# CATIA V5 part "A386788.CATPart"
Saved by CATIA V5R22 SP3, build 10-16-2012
Part number: EPXB2PB13N
Revision: A
Definition: A386788
Nomenclature: CONNECTOR, PLUG, SHELL, 2 CAVITY
Source: bought
Description: CONNECTOR, PLUG, SHELL, 2 CAVITY
Publications: "Logical Termination.1", "Logical Pin.1", "CaCP1", "CaCP A_generated(CaCP1)", "Ca A Coincident_generated(CaCP1)", "Ca A Direction_generated(CaCP1)", "CaCP2", "CaCP B_generated(CaCP2)", "Ca B Coincident_generated(CaCP2)", "Ca B Direction_generated(CaCP2)", "BaCP", "BaCP_generated(BaCP)", "Face_generated(BaCP)", "BaCP Coincident_generated(BaCP)", "BaCP Direction_generated(BaCP)"
Material "Density=.1010": density 2795.67 kg/m3
Bounding box of the stored display mesh (mm): x -44.006 to 44.006, y -14.097 to 21.844, z -9.512 to 9.512
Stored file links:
  C:\Users\u305772\OneDrive - Gulfstream Aerospace\AD PAG\Harness\A386788.CATPart
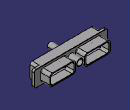
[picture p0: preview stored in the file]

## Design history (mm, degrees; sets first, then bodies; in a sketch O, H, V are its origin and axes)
Parameters
  PartNumber = "EPXB2PB13N"
  OtherKeywords = "CONNECTOR, SHELL, PLUG, 2 CAVITY"
  Comments = "SHELL, PLUG, 2 CAVITY, ALUMINUM ALLOY, NICKEL PLATED"
  CAGECode = "F0987"
  WeightComment = "CALCULATED FROM CATIA"
  WeightSource = "Calculated"
  Volume = 1.15248e-05 (volume) {= smartVolume(Body1)}
  Density = 2795.67 (density)
  Weight = 0.08
AxisSystem1 "CCP": origin (0, 21.844, 1.5011), X (0, 1, 0), Y (-1, 0, 0), Z (0, 0, 1)
Set1
  Point1 "CaCP A": type OnPlane, Support end face of Pocket2, RefPoint sketch element, H 0, V 0, Direction (1, 0, 0)
  Point2 "CaCP B": type OnPlane, Support end face of Pocket2, RefPoint sketch element, H 0, V 0, Direction (1, 0, 0)
  Line1 "Ca A Coincident": type PtDir, RefPoint Point1, Direction (0, 1, 0), Start 0, End 6.35
  Line2 "Ca A Direction": type PtDir, RefPoint Point1, Direction (0, 0, 1), Start 0, End 6.35
  Line3 "Ca B Coincident": type PtDir, RefPoint Point2, Direction (0, 1, 0), Start 0, End 6.35
  Line4 "Ca B Direction": type PtDir, RefPoint Point2, Direction (0, 0, 1), Start 0, End 6.35
  Point3 "CCP": type Center, Curve edge [end face of Pad4 | face of Pad4 from Sketch6.A2]
  Line5 "CCP Coincident": type PtDir, RefPoint Point3, Direction (0, 1, 0), Start 0, End 6.35
  Line6 "CCP Direction": type PtDir, RefPoint Point3, Direction (0, 0, 1), Start 0, End 6.35
  Point4 "BaCP": type OnPlane, Support start face of Pad1, H 0, V 0, Direction (1, 0, 0)
  Line7 "BaCP Coincident": type PtDir, RefPoint Point4, Direction (0, 1, 0), Start 0, End 6.35
  Line8 "BaCP Direction": type PtDir, RefPoint Point4, Direction (0, 0, 1), Start 0, End 6.35
Body1 (main body)
  Sketch1 on zx-plane, origin (0, 0, 0), H (-1, 0, 0), V (0, 0, 1)
    line L1 (37.9222, 6.9723) -> (37.9222, -6.9723)
    line L2 (35.3822, -9.5123) -> (-35.3822, -9.5123)
    line L3 (-37.9222, -6.9723) -> (-37.9222, 6.9723)
    line L4 (-35.3822, 9.5123) -> (35.3822, 9.5123)
    arc A1 centre (35.3822, 6.9723) radius 2.54 from (37.9222, 6.9723) to (35.3822, 9.5123) ccw
    arc A2 centre (35.3822, -6.9723) radius 2.54 from (37.9222, -6.9723) to (35.3822, -9.5123) cw
    arc A3 centre (-35.3822, -6.9723) radius 2.54 from (-35.3822, -9.5123) to (-37.9222, -6.9723) cw
    arc A4 centre (-35.3822, 6.9723) radius 2.54 from (-37.9222, 6.9723) to (-35.3822, 9.5123) cw
    radius A1 = 2.54
    radius A2 = 2.54 {= Sketch1.radius(A1)}
    radius A3 = 2.54 {= Sketch1.radius(A1)}
    radius A4 = 2.54 {= Sketch1.radius(A1)}
    distance L4 L2 = 19.0246
    distance L1 L3 = 75.8444
    vertical: L1 V, L3 V
    horizontal: L2 H, L4 H
    equidistance: L1 L3 O, L2 L4 O
    tangency: A1 L1, A1 L4, A2 L1, A2 L2, A3 L2, A3 L3, A4 L3, A4 L4
  Pad1: profile Sketch1, direction (0, 1, 0), length 8.001
  Sketch2 on end face of Pad1, origin (0, 8.001, 0), H (-1, 0, 0), V (0, 0, 1)
    line L1 (44.0055, 6.9723) -> (44.0055, -6.9723)
    line L2 (41.4655, -9.5123) -> (-41.4655, -9.5123)
    line L3 (-44.0055, -6.9723) -> (-44.0055, 6.9723)
    line L4 (-41.4655, 9.5123) -> (41.4655, 9.5123)
    arc A1 centre (41.4655, 6.9723) radius 2.54 from (44.0055, 6.9723) to (41.4655, 9.5123) ccw
    arc A2 centre (41.4655, -6.9723) radius 2.54 from (44.0055, -6.9723) to (41.4655, -9.5123) cw
    arc A3 centre (-41.4655, -6.9723) radius 2.54 from (-41.4655, -9.5123) to (-44.0055, -6.9723) cw
    arc A4 centre (-41.4655, 6.9723) radius 2.54 from (-44.0055, 6.9723) to (-41.4655, 9.5123) cw
    reference projected line E1 (35.3822, 9.5123) -> (-35.3822, 9.5123) from edge [face of Pad1 from Sketch1.L4 | end face of Pad1]
    radius A1 = 2.54
    radius A2 = 2.54 {= Sketch2.radius(A1)}
    radius A3 = 2.54 {= Sketch2.radius(A1)}
    radius A4 = 2.54 {= Sketch2.radius(A1)}
    distance L1 L3 = 88.011
    vertical: L1 V, L3 V
    horizontal: L2 H, L4 H
    equidistance: L1 L3 O, L2 L4 O
    tangency: A1 L1, A1 L4, A2 L1, A2 L2, A3 L2, A3 L3, A4 L3, A4 L4
    coincidence: L4 E1
  Pad2: profile Sketch2, direction (0, 1, 0), length 3.048
  Sketch3 on end face of Pad2, origin (0, 11.049, 0), H (-1, 0, 0), V (0, 0, 1)
    point P1 (-20.9233, 0)
    line L1 (-5.4737, 3.8608) -> (-5.4737, -3.8608)
    line L2 (-8.5725, -6.9596) -> (-33.274, -6.9596)
    line L3 (-36.3728, -3.8608) -> (-36.3728, 3.8608)
    line L4 (-33.274, 6.9596) -> (-8.5725, 6.9596)
    point P2 (-5.4737, 6.9596)
    point P3 (-5.4737, -6.9596)
    point P4 (-36.3728, -6.9596)
    point P5 (-36.3728, 6.9596)
    point P6 (5.4737, -6.9596)
    point P7 (5.4737, 6.9596)
    line L5 (5.4737, 3.8608) -> (5.4737, -3.8608)
    point P8 (36.3728, -6.9596)
    line L6 (8.5725, -6.9596) -> (33.274, -6.9596)
    point P9 (36.3728, 6.9596)
    line L7 (36.3728, -3.8608) -> (36.3728, 3.8608)
    line L8 (33.274, 6.9596) -> (8.5725, 6.9596)
    point P10 (20.9233, 0)
    arc A1 centre (-8.5725, 3.8608) radius 3.0988 from (-5.4737, 3.8608) to (-8.5725, 6.9596) ccw
    arc A2 centre (-8.5725, -3.8608) radius 3.0988 from (-5.4737, -3.8608) to (-8.5725, -6.9596) cw
    arc A3 centre (-33.274, -3.8608) radius 3.0988 from (-33.274, -6.9596) to (-36.3728, -3.8608) cw
    arc A4 centre (-33.274, 3.8608) radius 3.0988 from (-36.3728, 3.8608) to (-33.274, 6.9596) cw
    arc A5 centre (8.5725, -3.8608) radius 3.0988 from (5.4737, -3.8608) to (8.5725, -6.9596) ccw
    arc A6 centre (8.5725, 3.8608) radius 3.0988 from (5.4737, 3.8608) to (8.5725, 6.9596) cw
    arc A7 centre (33.274, -3.8608) radius 3.0988 from (33.274, -6.9596) to (36.3728, -3.8608) ccw
    arc A8 centre (33.274, 3.8608) radius 3.0988 from (36.3728, 3.8608) to (33.274, 6.9596) ccw
    distance L5 L1 = 10.9474
    distance L7 L3 = 72.7456
    distance L8 L6 = 13.9192
    radius A1 = 3.0988
    radius A2 = 3.0988 {= Sketch3.radius(A1)}
    radius A3 = 3.0988 {= Sketch3.radius(A1)}
    radius A4 = 3.0988 {= Sketch3.radius(A1)}
    radius A5 = 3.0988 {= Sketch3.radius(A1)}
    radius A6 = 3.0988 {= Sketch3.radius(A1)}
    radius A7 = 3.0988 {= Sketch3.radius(A1)}
    radius A8 = 3.0988 {= Sketch3.radius(A1)}
    coincidence: P1 H, L1 P2, L4 P2, L1 P3, L2 P3, L2 P4, L3 P4, L3 P5, L4 P5, L5 P6, L6 P6, L5 P7, L8 P7, L6 P8, L7 P8, L7 P9, L8 P9
    vertical: L1 V, L3 V
    horizontal: L2 H, L4 H
    equidistance: L1 L3 P1, L2 L4 P1
    symmetry: P3 P6 V, P2 P7 V, L1 L5 V, P4 P8 V, L2 L6 V, P5 P9 V, L3 L7 V, L4 L8 V, P1 P10 V
    tangency: A1 L1, A1 L4, A2 L1, A2 L2, A3 L2, A3 L3, A4 L3, A4 L4, A5 L5, A5 L6, A6 L5, A6 L8, A7 L6, A7 L7, A8 L7, A8 L8
  Pad3: profile Sketch3, direction (0, 1, 0), length 10.795
  Sketch4 on end face of Pad3, origin (0, 21.844, 0), H (-1, 0, 0), V (0, 0, 1)
    point P1 (-20.9233, 0)
    line L1 (-7.0739, 3.3274) -> (-7.0739, -3.3274)
    line L2 (-9.4615, -5.715) -> (-32.385, -5.715)
    line L3 (-34.7726, -3.3274) -> (-34.7726, 3.3274)
    line L4 (-32.385, 5.715) -> (-9.4615, 5.715)
    arc A1 centre (-9.4615, 3.3274) radius 2.3876 from (-7.0739, 3.3274) to (-9.4615, 5.715) ccw
    point P2 (-7.0739, 3.3274)
    point P3 (-9.4615, 5.715)
    arc A2 centre (-9.4615, -3.3274) radius 2.3876 from (-7.0739, -3.3274) to (-9.4615, -5.715) cw
    point P5 (-7.0739, -3.3274)
    point P6 (-9.4615, -5.715)
    arc A3 centre (-32.385, -3.3274) radius 2.3876 from (-32.385, -5.715) to (-34.7726, -3.3274) cw
    point P8 (-32.385, -5.715)
    point P9 (-34.7726, -3.3274)
    arc A4 centre (-32.385, 3.3274) radius 2.3876 from (-34.7726, 3.3274) to (-32.385, 5.715) cw
    point P11 (-34.7726, 3.3274)
    point P12 (-32.385, 5.715)
    point P14 (20.9233, 0)
    point P15 (7.0739, 3.3274)
    point P16 (9.4615, 5.715)
    point P18 (7.0739, -3.3274)
    point P19 (9.4615, -5.715)
    point P21 (32.385, -5.715)
    point P22 (34.7726, -3.3274)
    point P24 (34.7726, 3.3274)
    point P25 (32.385, 5.715)
    line L5 (7.0739, 3.3274) -> (7.0739, -3.3274)
    line L6 (9.4615, -5.715) -> (32.385, -5.715)
    line L7 (34.7726, -3.3274) -> (34.7726, 3.3274)
    line L8 (32.385, 5.715) -> (9.4615, 5.715)
    arc A5 centre (9.4615, 3.3274) radius 2.3876 from (7.0739, 3.3274) to (9.4615, 5.715) cw
    arc A6 centre (9.4615, -3.3274) radius 2.3876 from (7.0739, -3.3274) to (9.4615, -5.715) ccw
    arc A7 centre (32.385, -3.3274) radius 2.3876 from (32.385, -5.715) to (34.7726, -3.3274) ccw
    arc A8 centre (32.385, 3.3274) radius 2.3876 from (34.7726, 3.3274) to (32.385, 5.715) ccw
    reference projected line E1 (5.4737, 4.4196) -> (5.4737, -4.4196) from edge [face of Pad3 from Sketch3.L5 | end face of Pad3]
    reference projected line E2 (36.3728, -4.4196) -> (36.3728, 4.4196) from edge [face of Pad3 from Sketch3.L7 | end face of Pad3]
    radius A1 = 2.3876
    radius A2 = 2.3876 {= Sketch4.radius(A1)}
    radius A3 = 2.3876 {= Sketch4.radius(A1)}
    radius A4 = 2.3876 {= Sketch4.radius(A1)}
    distance L4 L2 = 11.43
    distance L5 E1 = 1.6002
    distance E2 L7 = 1.6002
    coincidence: P1 H
    vertical: L1 V, L3 V
    horizontal: L2 H, L4 H
    equidistance: L1 L3 P1, L2 L4 P1
    tangency: A1 L1, A1 L4, A2 L1, A2 L2, A3 L2, A3 L3, A4 L3, A4 L4
    symmetry: P1 P14 V, P2 P15 V, P3 P16 V, P5 P18 V, P6 P19 V, P8 P21 V, P9 P22 V, P11 P24 V, P12 P25 V, L1 L5 V, L2 L6 V, L3 L7 V, L4 L8 V, A1 A5 V, A2 A6 V, A3 A7 V, A4 A8 V
  Pocket1: profile Sketch4, direction (0, -1, 0), through (limit type 6)
  Sketch5 on start face of Pad1, origin (0, 0, 0), H (1, 0, 0), V (0, 0, 1)
    point P1 (-20.8661, 0)
    line L1 (-5.969, 5.2451) -> (-5.969, -5.2451)
    line L2 (-6.7564, -6.0325) -> (-34.9758, -6.0325)
    line L3 (-35.7632, -5.2451) -> (-35.7632, 5.2451)
    line L4 (-34.9758, 6.0325) -> (-6.7564, 6.0325)
    arc A1 centre (-6.7564, 5.2451) radius 0.7874 from (-5.969, 5.2451) to (-6.7564, 6.0325) ccw
    point P2 (-5.969, 5.2451)
    point P3 (-6.7564, 6.0325)
    arc A2 centre (-6.7564, -5.2451) radius 0.7874 from (-5.969, -5.2451) to (-6.7564, -6.0325) cw
    point P5 (-5.969, -5.2451)
    point P6 (-6.7564, -6.0325)
    arc A3 centre (-34.9758, -5.2451) radius 0.7874 from (-34.9758, -6.0325) to (-35.7632, -5.2451) cw
    point P8 (-34.9758, -6.0325)
    point P9 (-35.7632, -5.2451)
    arc A4 centre (-34.9758, 5.2451) radius 0.7874 from (-35.7632, 5.2451) to (-34.9758, 6.0325) cw
    point P11 (-35.7632, 5.2451)
    point P12 (-34.9758, 6.0325)
    reference projected line E1 (-37.9222, -6.8707) -> (-37.9222, 6.8707) from edge [start face of Pad1 | face of Pad1 from Sketch1.L1]
    point P14 (20.8661, 0)
    point P15 (5.969, 5.2451)
    point P16 (6.7564, 6.0325)
    point P18 (5.969, -5.2451)
    point P19 (6.7564, -6.0325)
    point P21 (34.9758, -6.0325)
    point P22 (35.7632, -5.2451)
    point P24 (35.7632, 5.2451)
    point P25 (34.9758, 6.0325)
    line L5 (5.969, 5.2451) -> (5.969, -5.2451)
    line L6 (6.7564, -6.0325) -> (34.9758, -6.0325)
    line L7 (35.7632, -5.2451) -> (35.7632, 5.2451)
    line L8 (34.9758, 6.0325) -> (6.7564, 6.0325)
    arc A5 centre (6.7564, 5.2451) radius 0.7874 from (5.969, 5.2451) to (6.7564, 6.0325) cw
    arc A6 centre (6.7564, -5.2451) radius 0.7874 from (5.969, -5.2451) to (6.7564, -6.0325) ccw
    arc A7 centre (34.9758, -5.2451) radius 0.7874 from (34.9758, -6.0325) to (35.7632, -5.2451) ccw
    arc A8 centre (34.9758, 5.2451) radius 0.7874 from (35.7632, 5.2451) to (34.9758, 6.0325) ccw
    radius A1 = 0.7874
    radius A2 = 0.7874 {= Sketch5.radius(A1)}
    radius A3 = 0.7874 {= Sketch5.radius(A1)}
    radius A4 = 0.7874 {= Sketch5.radius(A1)}
    distance L3 E1 = 2.159
    distance L5 L1 = 11.938
    distance L4 L2 = 12.065
    coincidence: P1 H
    vertical: L1 V, L3 V
    horizontal: L2 H, L4 H
    equidistance: L1 L3 P1, L2 L4 P1
    tangency: A1 L1, A1 L4, A2 L1, A2 L2, A3 L2, A3 L3, A4 L3, A4 L4
    symmetry: P1 P14 V, P2 P15 V, P3 P16 V, P5 P18 V, P6 P19 V, P8 P21 V, P9 P22 V, P11 P24 V, P12 P25 V, L1 L5 V, L2 L6 V, L3 L7 V, L4 L8 V, A1 A5 V, A2 A6 V, A3 A7 V, A4 A8 V
  Pocket2: profile Sketch5, direction (0, 1, 0), length 12.2428
  Sketch6 on end face of Pad2, origin (0, 11.049, 0), H (-1, 0, 0), V (0, 0, 1)
    circle A1 centre (0, 1.5011) radius 3.9751
    point P1 (0, 1.5011)
    circle A2 centre (0, 1.5011) radius 3.3401
    point P2 (20.9233, 0)
    reference projected line E1 (33.9852, 5.715) -> (7.8613, 5.715) from edge [end face of Pad3 | face of Pocket1 from Sketch4.L8]
    reference projected line E2 (7.8613, -5.715) -> (33.9852, -5.715) from edge [end face of Pad3 | face of Pocket1 from Sketch4.L6]
    reference projected line E3 (7.0739, 4.8006) -> (7.0739, -4.8006) from edge [end face of Pad3 | face of Pocket1 from Sketch4.L5]
    reference projected line E4 (34.7726, -4.8006) -> (34.7726, 4.8006) from edge [end face of Pad3 | face of Pocket1 from Sketch4.L7]
    radius A1 = 3.9751
    distance A2 A1 = 0.635
    distance P1 P2 V = 1.5011
    coincidence: P1 V
    equidistance: E1 E2 P2, E3 E4 P2
  Pad4: profile Sketch6, direction (0, 1, 0), up to end face of Pad3
  Sketch7 on start face of Pad1, origin (0, 0, 0), H (1, 0, 0), V (0, 0, 1)
    circle A1 centre (0, 1.5011) radius 3.429
    point P1 (0, 1.5011)
    reference projected circle E1 centre (0, 1.5011) radius 3.3401 from edge [end face of Pad4 | face of Pad4 from Sketch6.A2]
    radius A1 = 3.429
    coincidence: P1 V
    concentricity: P1 E1
  Pad5: profile Sketch7, direction (0, -1, 0), length 14.097
  Chamfer1: length 0.254, angle 45, on edge [face of Pad2 | end face of Pad2]; edge [start face of Pad2 | face of Pad2 from Sketch2.L1]; edge [start face of Pad2 | face of Pad2 from Sketch2.L3]; edge [face of Pad5 from Sketch7.A1 | end face of Pad5]; edge [end face of Pad3 | face of Pocket1 from Sketch4.L2]; edge [end face of Pad3 | face of Pocket1 from Sketch4.L6]
  Sketch8 on start face of Pad2, origin (0, 8.001, 0), H (1, 0, 0), V (0, 0, 1)
    line L1 (-41.7787, -1.016) -> (-40.9577, 1.016)
    line L2 (-40.9577, 1.016) -> (-40.716, 1.016)
    line L3 (-40.716, 1.016) -> (-39.895, -1.016)
    line L4 (-39.895, -1.016) -> (-40.2506, -1.016)
    line L5 (-40.2506, -1.016) -> (-40.4559, -0.508)
    line L6 (-40.4559, -0.508) -> (-41.2179, -0.508)
    line L7 (-41.2179, -0.508) -> (-41.4231, -1.016)
    point P8 (-41.4231, -1.016)
    line L8 (-41.4231, -1.016) -> (-41.7787, -1.016)
    arc A1 centre (40.8369, 0.4191) radius 0.5969 from (41.2619, 0) to (40.8369, 1.016) ccw
    arc A2 centre (40.8369, -0.4191) radius 0.5969 from (40.8369, -1.016) to (41.2619, 0) ccw
    line L9 (40.8369, 1.016) -> (40.0812, 1.016)
    line L10 (40.0812, 1.016) -> (40.0812, -1.016)
    line L11 (40.0812, -1.016) -> (40.8369, -1.016)
    point P15 (41.2619, 0)
    construction line L12 (40.8369, -0.4191) -> (40.8369, 0.4191)
    arc A3 centre (40.8369, 0.4191) radius 0.2413 from (40.8369, 0.1778) to (40.8369, 0.6604) ccw
    arc A4 centre (40.8369, -0.4191) radius 0.2413 from (40.8369, -0.6604) to (40.8369, -0.1778) ccw
    point P16 (40.8369, 0.6604)
    line L13 (40.8369, 0.6604) -> (40.4368, 0.6604)
    line L14 (40.4368, 0.6604) -> (40.4368, 0.1778)
    line L15 (40.4368, -0.6604) -> (40.8369, -0.6604)
    line L16 (40.8369, -0.1778) -> (40.4368, -0.1778)
    point P20 (40.8369, -0.1778)
    point P21 (40.4368, -0.1778)
    line L17 (40.8369, 0.1778) -> (40.4368, 0.1778)
    point P22 (40.8369, 0.1778)
    point P24 (40.8369, 0.1778)
    line L18 (40.4368, -0.1778) -> (40.4368, -0.6604)
    point P25 (40.8369, -0.1778)
    reference projected line E1 (43.7515, 6.9723) -> (43.7515, -6.9723) from edge [start face of Pad2 | face of Chamfer1]
    reference projected line E2 (37.9222, 6.9723) -> (37.9222, -6.9723) from edge [face of Pad1 from Sketch1.L3 | start face of Pad2]
    reference projected line E3 (37.9222, 6.9723) -> (37.9222, -6.9723) from edge [face of Pad1 from Sketch1.L3 | start face of Pad2]
    construction line L19 (-40.8369, 1.016) -> (-40.8369, -0.508)
    point P26 (-40.8369, 1.016)
    point P27 (-40.8369, -0.508)
    reference projected line E4 (-43.7515, -6.9723) -> (-43.7515, 6.9723) from edge [start face of Pad2 | face of Chamfer1]
    reference projected line E5 (-37.9222, -6.9723) -> (-37.9222, 6.9723) from edge [face of Pad1 from Sketch1.L1 | start face of Pad2]
    point P28 (-40.8369, 0.435)
    line L20 (-40.8369, 0.435) -> (-41.0742, -0.1524)
    line L21 (-41.0742, -0.1524) -> (-40.5995, -0.1524)
    line L22 (-40.5995, -0.1524) -> (-40.8369, 0.435)
    distance L14 L10 = 0.3556
    distance L13 L9 = 0.3556
    distance L16 L17 = 0.3556
    distance L15 L11 = 0.3556
    distance L9 L11 = 2.032
    distance L10 E3 = 2.159
    length L4 = 0.3556
    distance L6 L4 = 0.508
    angle L5 L7 = 44
    distance L21 L6 = 0.3556
    length L6 = 0.762
    horizontal: L2 H, L4 H, L6 H, L8 H, L9 H, L11 H, L13 H, L15 H, L21 H
    parallelism: L5 L3, L7 L1, L20 L1, L22 L3
    coincidence: P8 L4, P15 H, P16 L12, P20 A4, P20 L12, P21 L14, P22 A3, P22 L12, L12 P24, L14 L18, L12 P25, L11 L4, L2 L9, P28 L19, L22 L5, L20 L7, P20 P25, P22 P24
    tangency: L9 A1, L11 A2, L13 A3, L15 A4, L16 A4, L17 A3
    vertical: L10 V, L12 V, L14 V, L18 V, L19 V
    symmetry: L9 L11 H, E1 E2 L12, E4 E5 L19
    midpoint: P26 L2, P27 L6
  Pocket3: profile Sketch8, direction (0, 1, 0), length 0.0102
  Sketch9 on start face of Pad1, origin (0, 0, 0), H (1, 0, 0), V (0, 0, 1)
    construction line L1 (-20.9233, 6.0325) -> (-20.9233, -6.0325)
    point P1 (-20.9233, 6.0325)
    point P2 (-20.9233, -6.0325)
    construction line L2 (20.9233, 6.0325) -> (20.9233, -6.0325)
    point P3 (20.9233, 6.0325)
    point P4 (20.9233, -6.0325)
    reference projected line E1 (-34.7726, -3.3274) -> (-34.7726, 3.3274) from edge [face of Pocket1 from Sketch4.L7 | end face of Pocket2]
    reference projected line E2 (-7.0739, 3.3274) -> (-7.0739, -3.3274) from edge [face of Pocket1 from Sketch4.L5 | end face of Pocket2]
    reference projected line E3 (-6.7564, 6.0325) -> (-34.9758, 6.0325) from edge [start face of Pad1 | face of Pocket2 from Sketch5.L4]
    reference projected line E4 (-34.9758, -6.0325) -> (-6.7564, -6.0325) from edge [start face of Pad1 | face of Pocket2 from Sketch5.L2]
    reference projected line E5 (7.0739, 3.3274) -> (7.0739, -3.3274) from edge [end face of Pocket2 | face of Pocket1 from Sketch4.L1]
    reference projected line E6 (34.7726, -3.3274) -> (34.7726, 3.3274) from edge [end face of Pocket2 | face of Pocket1 from Sketch4.L3]
    reference projected line E7 (34.9758, 6.0325) -> (6.7564, 6.0325) from edge [start face of Pad1 | face of Pocket2 from Sketch5.L8]
    reference projected line E8 (6.7564, -6.0325) -> (34.9758, -6.0325) from edge [start face of Pad1 | face of Pocket2 from Sketch5.L6]
    circle A1 centre (-20.9233, 3.1623) radius 3.3734
    point P5 (-20.9233, 3.1623)
    circle A2 centre (24.7333, 3.1623) radius 3.3734
    point P6 (24.7333, 3.1623)
    construction line L3 (-20.9233, 3.1623) -> (24.7333, 3.1623)
    point P7 (17.1133, 3.1623)
    circle A3 centre (17.1133, 3.1623) radius 3.3734
    reference projected line E9 (-35.3822, 9.5123) -> (35.3822, 9.5123) from edge [start face of Pad1 | face of Pad1 from Sketch1.L4]
    distance E9 L3 = 6.35
    radius A1 = 3.3734
    radius A2 = 3.3734
    distance P7 P6 = 7.62
    vertical: L1 V, L2 V
    symmetry: E1 E2 L1, E5 E6 L2, A2 A3 L2
    coincidence: E3 P1, P2 E4, P3 E7, P4 E8, P5 L1
    horizontal: L3 H
  Pocket4: profile Sketch9, direction (0, 1, 0), length 14.2875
